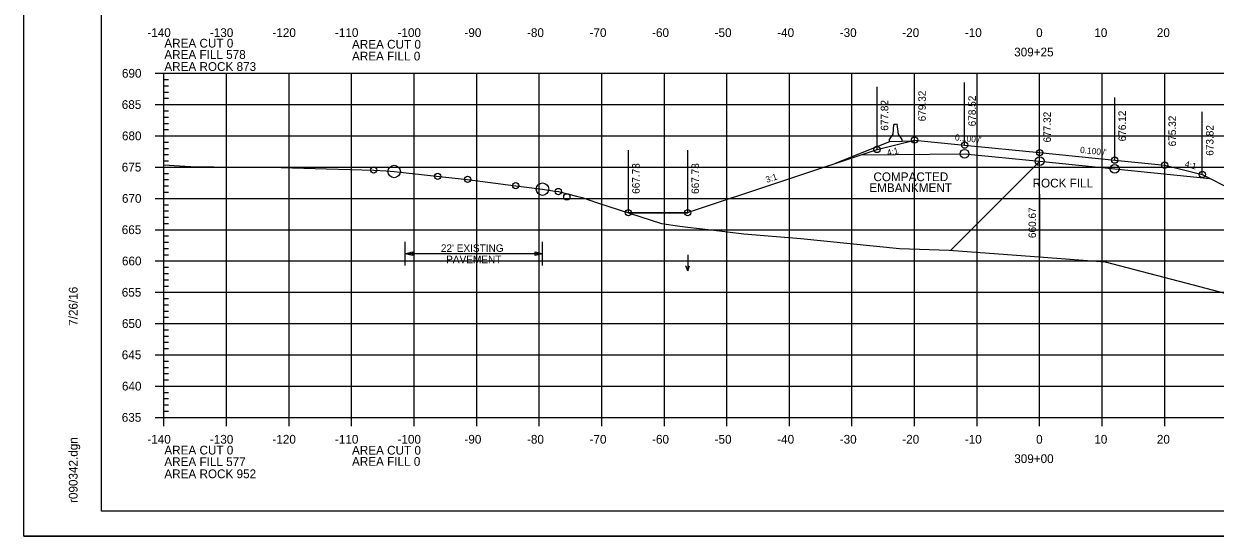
# Model space of a CAD drawing. Extents: x 1370515 to 1370849, y 383299 to 386073.
# Drawn here: x 1370515.4 to 1370705.9, y 384579.5 to 384661.3 of the extents above; entities that cross this region are included whole.
import ezdxf

# ---------------------------------------------------------------- set-up
doc = ezdxf.new("R2010")
doc.units = 0
for name, color, linetype in [('R_Alt Surface', 7, 'Continuous'), ('R_Axis', 7, 'Continuous'), ('R_Axis Annot', 7, 'Continuous'), ('R_Border', 7, 'Continuous'), ('R_Detour', 7, 'Continuous'), ('R_Exist Surface', 7, 'Continuous'), ('R_Fin Surface', 7, 'Continuous'), ('R_Grid', 7, 'Continuous'), ('R_No Plot', 7, 'Continuous'), ('R_ROW Annot', 7, 'Continuous'), ('R_Water', 7, 'Continuous'), ('R_Water Annot', 7, 'Continuous'), ('R_Xsect Elev', 7, 'Continuous'), ('R_Xsect Slope', 7, 'Continuous')]:
    doc.layers.add(name, color=color, linetype=linetype)

msp = doc.modelspace()

# ---------------------------------------------------------------- linework, layer by layer
at = {"layer": 'R_Alt Surface'}
msp.add_lwpolyline([(1370649.23, 384640.4), (1370665.8, 384640.58), (1370677.8, 384639.39), (1370689.8, 384638.18), (1370705.03, 384636.65)], dxfattribs=at)
at = {"layer": 'R_Axis'}
for p, q in [((1370536.4, 384653.44), (1370539.2, 384653.44)), ((1370537.8, 384598.44), (1370537.8, 384653.44)), ((1370537.8, 384652.44), (1370538.5, 384652.44)), ((1370537.8, 384651.44), (1370538.5, 384651.44)), ((1370537.8, 384650.44), (1370538.5, 384650.44)), ((1370536.4, 384648.44), (1370539.2, 384648.44)), ((1370537.8, 384649.44), (1370538.5, 384649.44)), ((1370537.8, 384647.44), (1370538.5, 384647.44)), ((1370537.8, 384646.44), (1370538.5, 384646.44)), ((1370537.8, 384645.44), (1370538.5, 384645.44)), ((1370537.8, 384644.44), (1370538.5, 384644.44)), ((1370536.4, 384643.44), (1370539.2, 384643.44)), ((1370537.8, 384642.44), (1370538.5, 384642.44)), ((1370537.8, 384641.44), (1370538.5, 384641.44)), ((1370537.8, 384640.44), (1370538.5, 384640.44)), ((1370537.8, 384639.44), (1370538.5, 384639.44)), ((1370536.4, 384638.44), (1370539.2, 384638.44)), ((1370537.8, 384637.44), (1370538.5, 384637.44)), ((1370537.8, 384636.44), (1370538.5, 384636.44)), ((1370537.8, 384635.44), (1370538.5, 384635.44)), ((1370536.4, 384633.44), (1370539.2, 384633.44)), ((1370537.8, 384634.44), (1370538.5, 384634.44)), ((1370537.8, 384632.44), (1370538.5, 384632.44)), ((1370537.8, 384631.44), (1370538.5, 384631.44)), ((1370537.8, 384630.44), (1370538.5, 384630.44)), ((1370537.8, 384629.44), (1370538.5, 384629.44)), ((1370536.4, 384628.44), (1370539.2, 384628.44)), ((1370537.8, 384627.44), (1370538.5, 384627.44)), ((1370537.8, 384626.44), (1370538.5, 384626.44)), ((1370537.8, 384625.44), (1370538.5, 384625.44)), ((1370536.4, 384623.44), (1370539.2, 384623.44)), ((1370537.8, 384624.44), (1370538.5, 384624.44)), ((1370537.8, 384622.44), (1370538.5, 384622.44)), ((1370537.8, 384621.44), (1370538.5, 384621.44)), ((1370537.8, 384620.44), (1370538.5, 384620.44)), ((1370537.8, 384619.44), (1370538.5, 384619.44)), ((1370536.4, 384618.44), (1370539.2, 384618.44)), ((1370537.8, 384617.44), (1370538.5, 384617.44)), ((1370537.8, 384616.44), (1370538.5, 384616.44)), ((1370537.8, 384615.44), (1370538.5, 384615.44)), ((1370537.8, 384614.44), (1370538.5, 384614.44)), ((1370536.4, 384613.44), (1370539.2, 384613.44)), ((1370537.8, 384612.44), (1370538.5, 384612.44)), ((1370537.8, 384611.44), (1370538.5, 384611.44)), ((1370537.8, 384610.44), (1370538.5, 384610.44)), ((1370536.4, 384608.44), (1370539.2, 384608.44)), ((1370537.8, 384609.44), (1370538.5, 384609.44)), ((1370537.8, 384607.44), (1370538.5, 384607.44)), ((1370537.8, 384606.44), (1370538.5, 384606.44)), ((1370537.8, 384605.44), (1370538.5, 384605.44)), ((1370537.8, 384604.44), (1370538.5, 384604.44)), ((1370536.4, 384603.44), (1370539.2, 384603.44)), ((1370537.8, 384602.44), (1370538.5, 384602.44)), ((1370537.8, 384601.44), (1370538.5, 384601.44)), ((1370537.8, 384600.44), (1370538.5, 384600.44)), ((1370537.8, 384597.04), (1370537.8, 384599.84)), ((1370537.8, 384599.44), (1370538.5, 384599.44)), ((1370547.8, 384597.04), (1370547.8, 384599.84)), ((1370557.8, 384597.04), (1370557.8, 384599.84)), ((1370567.8, 384597.04), (1370567.8, 384599.84)), ((1370577.8, 384597.04), (1370577.8, 384599.84)), ((1370587.8, 384597.04), (1370587.8, 384599.84)), ((1370597.8, 384597.04), (1370597.8, 384599.84)), ((1370607.8, 384597.04), (1370607.8, 384599.84)), ((1370617.8, 384597.04), (1370617.8, 384599.84)), ((1370627.8, 384597.04), (1370627.8, 384599.84)), ((1370637.8, 384597.04), (1370637.8, 384599.84)), ((1370647.8, 384597.04), (1370647.8, 384599.84)), ((1370657.8, 384597.04), (1370657.8, 384599.84)), ((1370667.8, 384597.04), (1370667.8, 384599.84)), ((1370677.8, 384597.04), (1370677.8, 384599.84)), ((1370687.8, 384597.04), (1370687.8, 384599.84)), ((1370697.8, 384597.04), (1370697.8, 384599.84)), ((1370536.4, 384598.44), (1370539.2, 384598.44)), ((1370537.8, 384598.44), (1370817.8, 384598.44))]:
    msp.add_line(p, q, dxfattribs=at)
at = {"layer": 'R_Border'}
for p, q in [((1370527.8, 384583.44), (1370527.8, 384788.9)), ((1370527.8, 384583.44), (1370527.8, 384583.44)), ((1370843.98, 384583.44), (1370527.8, 384583.44))]:
    msp.add_line(p, q, dxfattribs=at)
at = {"layer": 'R_Detour'}
for p, q in [((1370654.37, 384643.69), (1370654.51, 384645.28)), ((1370654.76, 384645.28), (1370654.51, 384645.28)), ((1370655.01, 384645.29), (1370654.76, 384645.28)), ((1370655.21, 384643.71), (1370655.01, 384645.29)), ((1370653.81, 384642.51), (1370645.11, 384639.03)), ((1370653.8, 384642.68), (1370653.8, 384642.68)), ((1370653.81, 384642.84), (1370654.37, 384643.69)), ((1370653.81, 384642.51), (1370653.81, 384642.84)), ((1370657.81, 384642.59), (1370653.81, 384642.51)), ((1370655.81, 384642.55), (1370653.81, 384642.51)), ((1370655.81, 384642.88), (1370655.21, 384643.71)), ((1370655.81, 384642.55), (1370655.81, 384642.88))]:
    msp.add_line(p, q, dxfattribs=at)
at = {"layer": 'R_Exist Surface'}
msp.add_lwpolyline([(1370537.8, 384638.8), (1370540.29, 384638.66), (1370543, 384638.5), (1370545.77, 384638.49), (1370551.27, 384638.43), (1370554.73, 384638.41), (1370563.81, 384638.16), (1370571.33, 384637.98), (1370573.3, 384637.84), (1370574.61, 384637.74), (1370581.85, 384636.96), (1370586.35, 384636.48), (1370594.06, 384635.47), (1370598.32, 384634.93), (1370599.99, 384634.67), (1370600.86, 384634.54), (1370603.75, 384633.81), (1370604.68, 384633.61), (1370607.09, 384632.76), (1370617.37, 384629.45), (1370620.28, 384629), (1370621.58, 384628.82), (1370625.26, 384628.43), (1370630.52, 384627.78), (1370639.62, 384627.01), (1370655.4, 384625.41), (1370663.31, 384625.18), (1370678.42, 384624.06), (1370688.26, 384623.29), (1370702.35, 384619.62), (1370708.43, 384618.03)], dxfattribs=at)
at = {"layer": 'R_Fin Surface'}
msp.add_line((1370677.82, 384639.38), (1370663.61, 384625.16), dxfattribs=at)
msp.add_lwpolyline([(1370612.05, 384631.17), (1370621.52, 384631.17), (1370651.8, 384641.26), (1370657.8, 384642.76), (1370665.8, 384641.96), (1370677.8, 384640.76), (1370689.8, 384639.56), (1370697.8, 384638.76), (1370703.8, 384637.26), (1370708.65, 384634.83), (1370745.92, 384616.2)], dxfattribs=at)
at = {"layer": 'R_Grid'}
for p, q in [((1370537.8, 384653.44), (1370817.8, 384653.44)), ((1370537.8, 384598.44), (1370537.8, 384653.44)), ((1370547.8, 384598.44), (1370547.8, 384653.44)), ((1370557.8, 384598.44), (1370557.8, 384653.44)), ((1370567.8, 384598.44), (1370567.8, 384653.44)), ((1370577.8, 384598.44), (1370577.8, 384653.44)), ((1370587.8, 384598.44), (1370587.8, 384653.44)), ((1370597.8, 384598.44), (1370597.8, 384653.44)), ((1370607.8, 384598.44), (1370607.8, 384653.44)), ((1370617.8, 384598.44), (1370617.8, 384653.44)), ((1370627.8, 384598.44), (1370627.8, 384653.44)), ((1370637.8, 384598.44), (1370637.8, 384653.44)), ((1370647.8, 384598.44), (1370647.8, 384653.44)), ((1370657.8, 384598.44), (1370657.8, 384653.44)), ((1370667.8, 384598.44), (1370667.8, 384653.44)), ((1370677.8, 384598.44), (1370677.8, 384653.44)), ((1370687.8, 384598.44), (1370687.8, 384653.44)), ((1370697.8, 384598.44), (1370697.8, 384653.44)), ((1370537.8, 384648.44), (1370817.8, 384648.44)), ((1370537.8, 384643.44), (1370817.8, 384643.44)), ((1370537.8, 384638.44), (1370817.8, 384638.44)), ((1370537.8, 384633.44), (1370817.8, 384633.44)), ((1370537.8, 384628.44), (1370817.8, 384628.44)), ((1370537.8, 384623.44), (1370817.8, 384623.44)), ((1370537.8, 384618.44), (1370817.8, 384618.44)), ((1370537.8, 384613.44), (1370817.8, 384613.44)), ((1370537.8, 384608.44), (1370817.8, 384608.44)), ((1370537.8, 384603.44), (1370817.8, 384603.44)), ((1370537.8, 384598.44), (1370817.8, 384598.44))]:
    msp.add_line(p, q, dxfattribs=at)
at = {"layer": 'R_No Plot'}
msp.add_line((1370515.4, 384579.46), (1370848.73, 384579.46), dxfattribs=at)
for points in [[(1370515.39, 384792.79), (1370848.73, 384792.79), (1370848.73, 384579.45), (1370515.39, 384579.45)], [(1370761.72, 384788.9), (1370761.72, 384779.02), (1370797.45, 384779.02), (1370797.45, 384776.1), (1370820.65, 384776.1), (1370820.65, 384752.88), (1370843.98, 384752.88), (1370843.98, 384583.44), (1370527.8, 384583.44), (1370527.8, 384788.9)]]:
    msp.add_lwpolyline(points, close=True, dxfattribs=at)
for centre, radius in [((1370657.8, 384642.76), 0.5), ((1370665.8, 384641.96), 0.5), ((1370651.8, 384641.26), 0.5), ((1370651.8, 384641.26), 0.5), ((1370665.8, 384640.58), 0.7), ((1370677.8, 384640.76), 0.5), ((1370571.33, 384637.98), 0.5), ((1370574.61, 384637.74), 1), ((1370677.8, 384639.39), 0.7), ((1370677.8, 384639.39), 0.7), ((1370689.8, 384638.18), 0.7), ((1370689.8, 384639.56), 0.5), ((1370697.8, 384638.76), 0.5), ((1370581.57, 384636.96), 0.5), ((1370586.35, 384636.48), 0.5), ((1370703.8, 384637.26), 0.5), ((1370703.8, 384637.26), 0.5), ((1370594.03, 384635.48), 0.5), ((1370598.32, 384634.93), 1), ((1370600.86, 384634.54), 0.5), ((1370602.21, 384633.69), 0.5), ((1370612.05, 384631.17), 0.5), ((1370621.54, 384631.16), 0.5)]:
    msp.add_circle(centre, radius, dxfattribs=at)
at = {"layer": 'R_ROW Annot'}
for p, q in [((1370576.34, 384622.71), (1370576.34, 384626.48)), ((1370598.34, 384622.71), (1370598.34, 384626.48)), ((1370598.34, 384624.59), (1370576.34, 384624.59))]:
    msp.add_line(p, q, dxfattribs=at)
for points in [[(1370577.54, 384624.29), (1370576.34, 384624.59), (1370577.54, 384624.89)], [(1370597.14, 384624.89), (1370598.34, 384624.59), (1370597.14, 384624.29)]]:
    msp.add_lwpolyline(points, close=True, dxfattribs=at)
at = {"layer": 'R_Water'}
msp.add_line((1370612.07, 384631.16), (1370621.54, 384631.16), dxfattribs=at)
at = {"layer": 'R_Water Annot'}
for p, q in [((1370621.53, 384624.4), (1370621.53, 384621.89)), ((1370621.53, 384621.89), (1370621.25, 384622.66)), ((1370621.53, 384621.89), (1370621.81, 384622.66))]:
    msp.add_line(p, q, dxfattribs=at)
at = {"layer": 'R_Xsect Elev'}
for p, q in [((1370657.8, 384642.76), (1370657.8, 384652.76)), ((1370665.8, 384641.96), (1370665.8, 384651.96)), ((1370651.8, 384641.26), (1370651.8, 384651.26)), ((1370677.8, 384639.39), (1370677.8, 384649.39)), ((1370689.8, 384639.56), (1370689.8, 384649.56)), ((1370697.8, 384638.76), (1370697.8, 384648.76)), ((1370703.8, 384637.26), (1370703.8, 384647.26)), ((1370612.05, 384631.17), (1370612.05, 384641.17)), ((1370621.54, 384631.16), (1370621.54, 384641.16)), ((1370677.82, 384624.1), (1370677.82, 384634.1))]:
    msp.add_line(p, q, dxfattribs=at)

# ---------------------------------------------------------------- texts
at = {"layer": 'R_Axis'}
msp.add_text('-', height=0.0001, dxfattribs=at).set_placement((1370537.8, 384598.44))
at = {"layer": 'R_Axis Annot'}
for s, p in [('-140', (1370535.14, 384659.24)), ('-130', (1370545.14, 384659.24)), ('-120', (1370555.14, 384659.24)), ('-110', (1370565.14, 384659.24)), ('-100', (1370575.14, 384659.24)), ('-90', (1370585.84, 384659.24)), ('-80', (1370595.84, 384659.24)), ('-70', (1370605.84, 384659.24)), ('-60', (1370615.84, 384659.24)), ('-50', (1370625.84, 384659.24)), ('-40', (1370635.84, 384659.24)), ('-30', (1370645.84, 384659.24)), ('-20', (1370655.84, 384659.24)), ('-10', (1370665.84, 384659.24)), ('0', (1370677.24, 384659.24)), ('10', (1370686.54, 384659.24)), ('20', (1370696.54, 384659.24)), ('AREA CUT 0', (1370537.86, 384657.55)), ('AREA CUT 0', (1370567.86, 384657.38)), ('309+25', (1370673.73, 384656.14)), ('AREA FILL 578', (1370537.86, 384655.74)), ('AREA FILL 0', (1370567.86, 384655.49)), ('690', (1370531.08, 384652.74)), ('AREA ROCK 873', (1370537.86, 384653.82)), ('685', (1370531.05, 384647.74)), ('680', (1370531.08, 384642.74)), ('675', (1370531.05, 384637.74)), ('COMPACTED', (1370651.23, 384636.2)), ('ROCK FILL', (1370676.67, 384635.19)), ('EMBANKMENT', (1370650.57, 384634.45)), ('670', (1370531.08, 384632.74)), ('665', (1370531.05, 384627.74)), ('660', (1370531.08, 384622.74)), ('655', (1370531.05, 384617.74)), ('650', (1370531.08, 384612.74)), ('645', (1370531.05, 384607.74)), ('640', (1370531.08, 384602.74)), ('635', (1370531.05, 384597.74)), ('-140', (1370535.14, 384594.24)), ('-130', (1370545.14, 384594.24)), ('-120', (1370555.14, 384594.24)), ('-110', (1370565.14, 384594.24)), ('-100', (1370575.14, 384594.24)), ('-90', (1370585.84, 384594.24)), ('-80', (1370595.84, 384594.24)), ('-70', (1370605.84, 384594.24)), ('-60', (1370615.84, 384594.24)), ('-50', (1370625.84, 384594.24)), ('-40', (1370635.84, 384594.24)), ('-30', (1370645.84, 384594.24)), ('-20', (1370655.84, 384594.24)), ('-10', (1370665.84, 384594.24)), ('0', (1370677.24, 384594.24)), ('10', (1370686.54, 384594.24)), ('20', (1370696.54, 384594.24)), ('AREA CUT 0', (1370537.86, 384592.51)), ('AREA CUT 0', (1370567.86, 384592.49)), ('AREA FILL 577', (1370537.86, 384590.66)), ('AREA FILL 0', (1370567.86, 384590.7)), ('309+00', (1370673.74, 384591.14)), ('AREA ROCK 952', (1370537.86, 384588.72))]:
    msp.add_text(s, height=1.4, dxfattribs=at).set_placement(p)
at = {"layer": 'R_Border'}
for s, p in [('7/26/16', (1370523.99, 384613.08)), ('r090342.dgn', (1370523.99, 384584.76))]:
    msp.add_text(s, height=1.4, rotation=90, dxfattribs=at).set_placement(p)
at = {"layer": 'R_No Plot'}
for p in [(1370545.73, 384638.44), (1370554.69, 384638.36), (1370604.64, 384633.56), (1370617.32, 384629.4), (1370630.48, 384627.73), (1370663.27, 384625.13), (1370688.22, 384623.24)]:
    msp.add_text('+', height=0.1, dxfattribs=at).set_placement(p)
at = {"layer": 'R_ROW Annot'}
for s, p in [("22' EXISTING", (1370582.07, 384624.89)), ('PAVEMENT', (1370582.92, 384623.09))]:
    msp.add_text(s, height=1.2, dxfattribs=at).set_placement(p)
at = {"layer": 'R_Xsect Elev'}
for s, p in [('679.32', (1370659.6, 384645.76)), ('677.82', (1370653.6, 384644.26)), ('678.52', (1370667.6, 384644.96)), ('677.32', (1370679.6, 384642.39)), ('676.12', (1370691.6, 384642.56)), ('675.32', (1370699.6, 384641.76)), ('673.82', (1370705.6, 384640.26)), ('667.73', (1370613.85, 384634.17)), ('667.73', (1370623.34, 384634.16)), ('660.67', (1370677.22, 384627.1))]:
    msp.add_text(s, height=1.2, rotation=90, dxfattribs=at).set_placement(p)
at = {"layer": 'R_Xsect Slope'}
for s, rotation, p in [("0.100'/'", 354.2894, (1370664.23, 384642.72)), ('4:1', 14.0362, (1370653.52, 384640.22)), ("0.100'/'", 354.2894, (1370684.23, 384640.72)), ('4:1', 345.9638, (1370700.92, 384638.5)), ('3:1', 18.4349, (1370634.18, 384635.91))]:
    msp.add_text(s, height=1, rotation=rotation, dxfattribs=at).set_placement(p)

doc.saveas('drawing.dxf')
